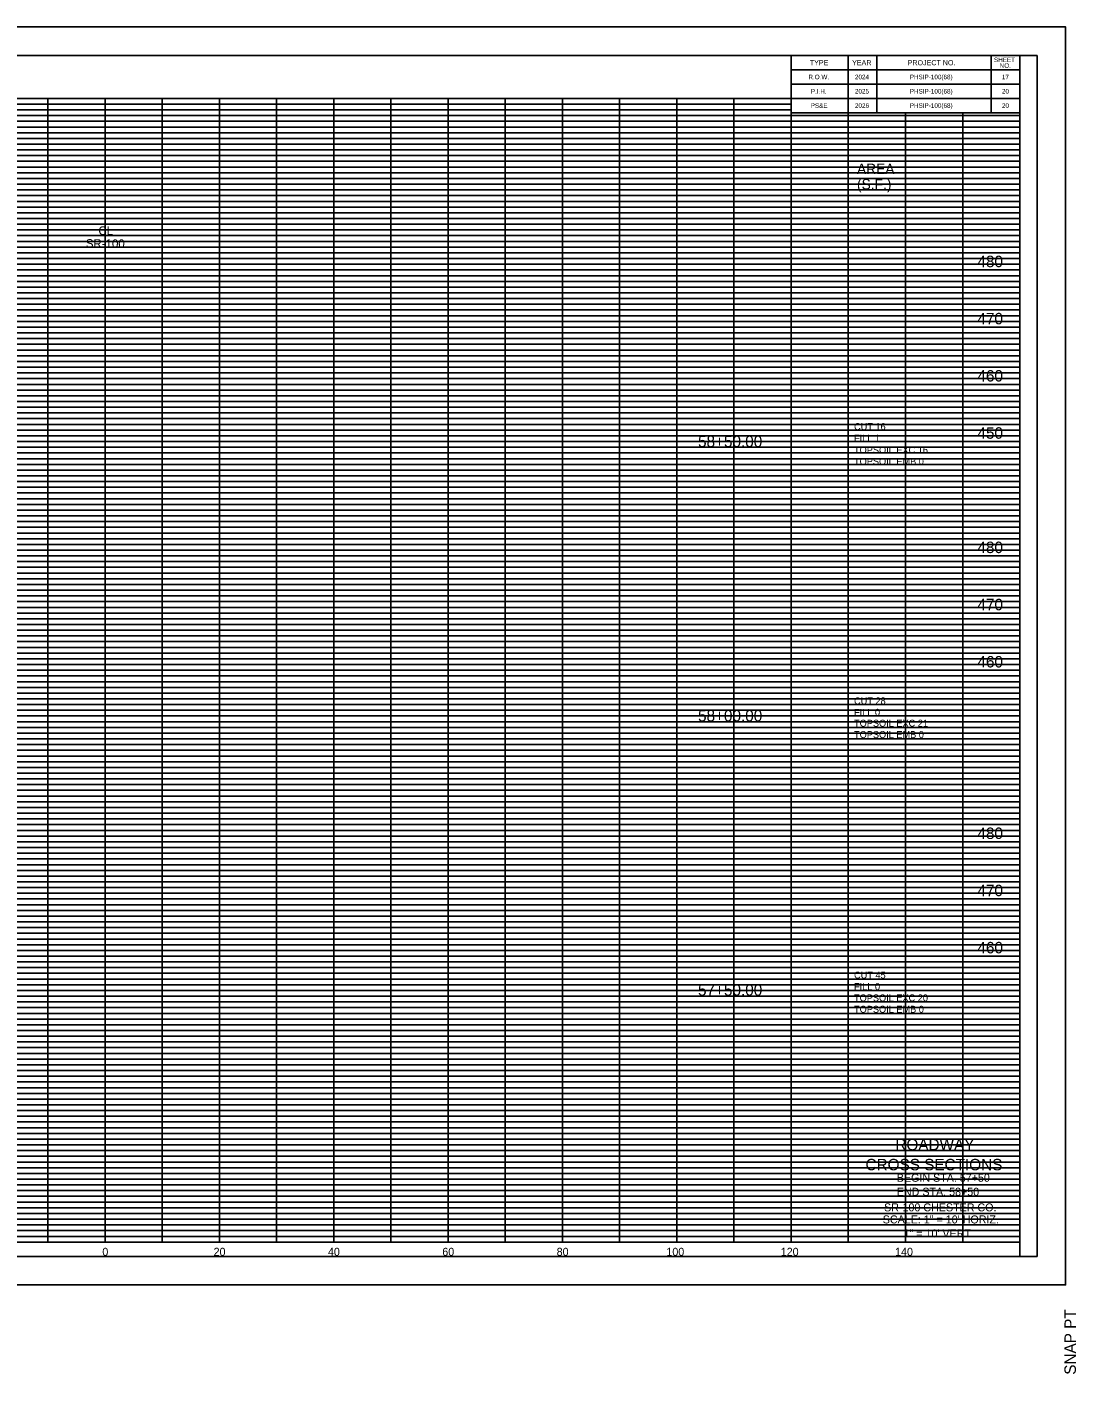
# Model space of a CAD drawing. Extents: x 37 to 1710, y 707 to 2305.
# Drawn here: x 1146.3 to 1329.8, y 976.9 to 1212.5 of the extents above; entities that cross this region are included whole.
import ezdxf

# ---------------------------------------------------------------- set-up
doc = ezdxf.new("R2010")
doc.units = 0
for name, color, linetype in [('DESIGN - DRAINAGE - Special Ditch Width Text', 7, 'Continuous'), ('DESIGN - SCRATCH - User 1', 7, 'Continuous'), ('DESIGN - SHEET - Corner Text', 7, 'Continuous'), ('DESIGN - SHEET - Light Grid', 7, 'Continuous'), ('DESIGN - SHEET - Linework', 7, 'Continuous'), ('DESIGN - SHEET - Plot Shape', 7, 'Continuous'), ('DESIGN - TYPICAL - Text', 7, 'Continuous')]:
    doc.layers.add(name, color=color, linetype=linetype)

msp = doc.modelspace()

# ---------------------------------------------------------------- linework, layer by layer
at = {"layer": 'DESIGN - SCRATCH - User 1'}
for p, q in [((1285, 1203.75), (1285, 1203.75)), ((1292.5, 1203.75), (1292.5, 1203.75)), ((1305, 1203.75), (1305, 1203.75)), ((1317.5, 1203.75), (1317.5, 1203.75)), ((1285, 1201.25), (1285, 1201.25)), ((1292.5, 1201.25), (1292.5, 1201.25)), ((1305, 1201.25), (1305, 1201.25)), ((1317.5, 1201.25), (1317.5, 1201.25))]:
    msp.add_line(p, q, dxfattribs=at)
at = {"layer": 'DESIGN - SHEET - Light Grid'}
for p, q in [((1000, 1199), (1280, 1199)), ((1000, 1198), (1280, 1198)), ((1000, 1197), (1320, 1197)), ((1000, 1196), (1320, 1196)), ((1000, 1195), (1320, 1195)), ((1000, 1194), (1320, 1194)), ((1000, 1193), (1320, 1193)), ((1000, 1192), (1320, 1192)), ((1000, 1191), (1320, 1191)), ((1000, 1189), (1320, 1189)), ((1000, 1188), (1320, 1188)), ((1000, 1187), (1320, 1187)), ((1000, 1186), (1320, 1186)), ((1000, 1185), (1320, 1185)), ((1000, 1184), (1320, 1184)), ((1000, 1183), (1320, 1183)), ((1000, 1182), (1320, 1182)), ((1000, 1181), (1320, 1181)), ((1000, 1179), (1320, 1179)), ((1000, 1178), (1320, 1178)), ((1000, 1177), (1320, 1177)), ((1000, 1176), (1320, 1176)), ((1000, 1175), (1320, 1175)), ((1000, 1174), (1320, 1174)), ((1000, 1173), (1320, 1173)), ((1000, 1172), (1320, 1172)), ((1000, 1171), (1320, 1171)), ((1000, 1169), (1320, 1169)), ((1000, 1168), (1320, 1168)), ((1000, 1167), (1320, 1167)), ((1000, 1166), (1320, 1166)), ((1000, 1165), (1320, 1165)), ((1000, 1164), (1320, 1164)), ((1000, 1163), (1320, 1163)), ((1000, 1162), (1320, 1162)), ((1000, 1161), (1320, 1161)), ((1000, 1159), (1320, 1159)), ((1000, 1158), (1320, 1158)), ((1000, 1157), (1320, 1157)), ((1000, 1156), (1320, 1156)), ((1000, 1155), (1320, 1155)), ((1000, 1154), (1320, 1154)), ((1000, 1153), (1320, 1153)), ((1000, 1152), (1320, 1152)), ((1000, 1151), (1320, 1151)), ((1000, 1149), (1320, 1149)), ((1000, 1148), (1320, 1148)), ((1000, 1147), (1320, 1147)), ((1000, 1146), (1320, 1146)), ((1000, 1145), (1320, 1145)), ((1000, 1144), (1320, 1144)), ((1000, 1143), (1320, 1143)), ((1000, 1142), (1320, 1142)), ((1000, 1141), (1320, 1141)), ((1000, 1139), (1320, 1139)), ((1000, 1138), (1320, 1138)), ((1000, 1137), (1320, 1137)), ((1000, 1136), (1320, 1136)), ((1000, 1135), (1320, 1135)), ((1000, 1134), (1320, 1134)), ((1000, 1133), (1320, 1133)), ((1000, 1132), (1320, 1132)), ((1000, 1131), (1320, 1131)), ((1000, 1129), (1320, 1129)), ((1000, 1128), (1320, 1128)), ((1000, 1127), (1320, 1127)), ((1000, 1126), (1320, 1126)), ((1000, 1125), (1320, 1125)), ((1000, 1124), (1320, 1124)), ((1000, 1123), (1320, 1123)), ((1000, 1122), (1320, 1122)), ((1000, 1121), (1320, 1121)), ((1000, 1119), (1320, 1119)), ((1000, 1118), (1320, 1118)), ((1000, 1117), (1320, 1117)), ((1000, 1116), (1320, 1116)), ((1000, 1115), (1320, 1115)), ((1000, 1114), (1320, 1114)), ((1000, 1113), (1320, 1113)), ((1000, 1112), (1320, 1112)), ((1000, 1111), (1320, 1111)), ((1000, 1109), (1320, 1109)), ((1000, 1108), (1320, 1108)), ((1000, 1107), (1320, 1107)), ((1000, 1106), (1320, 1106)), ((1000, 1105), (1320, 1105)), ((1000, 1104), (1320, 1104)), ((1000, 1103), (1320, 1103)), ((1000, 1102), (1320, 1102)), ((1000, 1101), (1320, 1101)), ((1000, 1099), (1320, 1099)), ((1000, 1098), (1320, 1098)), ((1000, 1097), (1320, 1097)), ((1000, 1096), (1320, 1096)), ((1000, 1095), (1320, 1095)), ((1000, 1094), (1320, 1094)), ((1000, 1093), (1320, 1093)), ((1000, 1092), (1320, 1092)), ((1000, 1091), (1320, 1091)), ((1000, 1089), (1320, 1089)), ((1000, 1088), (1320, 1088)), ((1000, 1087), (1320, 1087)), ((1000, 1086), (1320, 1086)), ((1000, 1085), (1320, 1085)), ((1000, 1084), (1320, 1084)), ((1000, 1083), (1320, 1083)), ((1000, 1082), (1320, 1082)), ((1000, 1081), (1320, 1081)), ((1000, 1079), (1320, 1079)), ((1000, 1078), (1320, 1078)), ((1000, 1077), (1320, 1077)), ((1000, 1076), (1320, 1076)), ((1000, 1075), (1320, 1075)), ((1000, 1074), (1320, 1074)), ((1000, 1073), (1320, 1073)), ((1000, 1072), (1320, 1072)), ((1000, 1071), (1320, 1071)), ((1000, 1069), (1320, 1069)), ((1000, 1068), (1320, 1068)), ((1000, 1067), (1320, 1067)), ((1000, 1066), (1320, 1066)), ((1000, 1065), (1320, 1065)), ((1000, 1064), (1320, 1064)), ((1000, 1063), (1320, 1063)), ((1000, 1062), (1320, 1062)), ((1000, 1061), (1320, 1061)), ((1000, 1059), (1320, 1059)), ((1000, 1058), (1320, 1058)), ((1000, 1057), (1320, 1057)), ((1000, 1056), (1320, 1056)), ((1000, 1055), (1320, 1055)), ((1000, 1054), (1320, 1054)), ((1000, 1053), (1320, 1053)), ((1000, 1052), (1320, 1052)), ((1000, 1051), (1320, 1051)), ((1000, 1049), (1320, 1049)), ((1000, 1048), (1320, 1048)), ((1000, 1047), (1320, 1047)), ((1000, 1046), (1320, 1046)), ((1000, 1045), (1320, 1045)), ((1000, 1044), (1320, 1044)), ((1000, 1043), (1320, 1043)), ((1000, 1042), (1320, 1042)), ((1000, 1041), (1320, 1041)), ((1000, 1039), (1320, 1039)), ((1000, 1038), (1320, 1038)), ((1000, 1037), (1320, 1037)), ((1000, 1036), (1320, 1036)), ((1000, 1035), (1320, 1035)), ((1000, 1034), (1320, 1034)), ((1000, 1033), (1320, 1033)), ((1000, 1032), (1320, 1032)), ((1000, 1031), (1320, 1031)), ((1000, 1029), (1320, 1029)), ((1000, 1028), (1320, 1028)), ((1000, 1027), (1320, 1027)), ((1000, 1026), (1320, 1026)), ((1000, 1025), (1320, 1025)), ((1000, 1024), (1320, 1024)), ((1000, 1023), (1320, 1023)), ((1000, 1022), (1320, 1022)), ((1000, 1021), (1320, 1021)), ((1000, 1019), (1320, 1019)), ((1000, 1018), (1320, 1018)), ((1000, 1017), (1320, 1017)), ((1000, 1016), (1320, 1016)), ((1000, 1015), (1320, 1015)), ((1000, 1014), (1320, 1014)), ((1000, 1013), (1320, 1013)), ((1000, 1012), (1320, 1012)), ((1000, 1011), (1320, 1011)), ((1000, 1009), (1320, 1009)), ((1000, 1008), (1320, 1008)), ((1000, 1007), (1320, 1007)), ((1000, 1006), (1320, 1006)), ((1000, 1005), (1320, 1005)), ((1000, 1004), (1320, 1004)), ((1000, 1003), (1320, 1003)), ((1000, 1002), (1320, 1002)), ((1000, 1001), (1320, 1001))]:
    msp.add_line(p, q, dxfattribs=at)
at = {"layer": 'DESIGN - SHEET - Linework'}
for p, q in [((1320, 1207.5), (1280, 1207.5)), ((1280, 1200), (1280, 1207.5)), ((1290, 1200), (1290, 1207.5)), ((1295, 1197.5), (1295, 1207.5)), ((1315, 1197.5), (1315, 1207.5)), ((1320, 1200), (1320, 1207.5)), ((1320, 1205), (1280, 1205)), ((1320, 1202.5), (1280, 1202.5)), ((1000, 1200), (1320, 1200)), ((1150, 1000), (1150, 1200)), ((1160, 1000), (1160, 1200)), ((1170, 1000), (1170, 1200)), ((1180, 1000), (1180, 1200)), ((1190, 1000), (1190, 1200)), ((1200, 1000), (1200, 1200)), ((1210, 1000), (1210, 1200)), ((1220, 1000), (1220, 1200)), ((1230, 1000), (1230, 1200)), ((1240, 1000), (1240, 1200)), ((1250, 1000), (1250, 1200)), ((1260, 1000), (1260, 1200)), ((1270, 1000), (1270, 1200)), ((1280, 1000), (1280, 1200)), ((1290, 1000), (1290, 1200)), ((1320, 1197.5), (1280, 1197.5)), ((1300, 1000), (1300, 1197.5)), ((1310, 1000), (1310, 1197.5)), ((1000, 1190), (1320, 1190)), ((1000, 1180), (1320, 1180)), ((1000, 1170), (1320, 1170)), ((1000, 1160), (1320, 1160)), ((1000, 1150), (1320, 1150)), ((1000, 1140), (1320, 1140)), ((1000, 1130), (1320, 1130)), ((1000, 1120), (1320, 1120)), ((1000, 1110), (1320, 1110)), ((1000, 1100), (1320, 1100)), ((1000, 1090), (1320, 1090)), ((1000, 1080), (1320, 1080)), ((1000, 1070), (1320, 1070)), ((1000, 1060), (1320, 1060)), ((1000, 1050), (1320, 1050)), ((1000, 1040), (1320, 1040)), ((1000, 1030), (1320, 1030)), ((1000, 1020), (1320, 1020)), ((1000, 1010), (1320, 1010)), ((1000, 1000), (1320, 1000))]:
    msp.add_line(p, q, dxfattribs=at)
for points in [[(988, 1212.5), (1328, 1212.5), (1328, 992.5), (988, 992.5)], [(1000, 1207.5), (1320, 1207.5), (1320, 997.5), (1000, 997.5)]]:
    msp.add_lwpolyline(points, close=True, dxfattribs=at)
at = {"layer": 'DESIGN - SHEET - Plot Shape'}
msp.add_lwpolyline([(993, 1207.5), (1323, 1207.5), (1323, 997.5), (993, 997.5)], close=True, dxfattribs=at)

# ---------------------------------------------------------------- texts
at = {"layer": 'DESIGN - DRAINAGE - Special Ditch Width Text'}
for s, p in [('CL', (1158.85, 1176.13)), ('SR-100', (1156.64, 1173.89))]:
    msp.add_text(s, height=1.5, rotation=359.6675, dxfattribs=at).set_placement(p)
at = {"layer": 'DESIGN - SHEET - Corner Text'}
for s, height, p in [('R.O.W.', 0.8, (1283.02, 1203.35)), ('2024', 0.8, (1291.16, 1203.35)), ('PHSIP-100(68)', 0.8, (1300.75, 1203.35)), ('17', 0.8, (1316.86, 1203.35)), ('P.I.H.', 0.8, (1283.45, 1200.85)), ('2025', 0.8, (1291.16, 1200.85)), ('PHSIP-100(68)', 0.8, (1300.75, 1200.85)), ('20', 0.8, (1316.87, 1200.85)), ('PS&E', 0.8, (1283.42, 1198.35)), ('2026', 0.8, (1291.16, 1198.35)), ('PHSIP-100(68)', 0.8, (1300.75, 1198.35)), ('20', 0.8, (1316.87, 1198.35)), ('ROADWAY ', 2, (1298.23, 1016.05)), ('CROSS SECTIONS', 2, (1293.01, 1012.55)), ('BEGIN STA. 57+50', 1.4, (1298.47, 1010.55)), ('END STA. 58+50', 1.4, (1298.47, 1008.1)), ('SR-100 CHESTER CO.', 1.4, (1296.25, 1005.37)), ('SCALE: 1" = 10\' HORIZ.', 1.4, (1296.02, 1003.26)), ('       1" = 10\' VERT.   ', 1.4, (1296.02, 1000.81))]:
    msp.add_text(s, height=height, dxfattribs=at).set_placement(p)
msp.add_text('SNAP PT  ', height=2, rotation=90, dxfattribs=at).set_placement((1329.8, 976.8))
at = {"layer": 'DESIGN - SHEET - Light Grid'}
for s, height, p in [('TYPE', 0.9, (1283.26, 1205.8)), ('YEAR', 0.9, (1290.66, 1205.8)), ('PROJECT NO.', 0.9, (1300.38, 1205.8)), ('SHEET', 0.8, (1315.47, 1206.35)), ('NO.', 0.8, (1316.47, 1205.35))]:
    msp.add_text(s, height=height, dxfattribs=at).set_placement(p)
at = {"layer": 'DESIGN - TYPICAL - Text'}
for s, height, p in [('AREA ', 1.8, (1291.52, 1186.79)), ('(S.F.)', 1.8, (1291.52, 1184.09)), ('     480     ', 2, (1308.87, 1170.49)), ('     470     ', 2, (1308.87, 1160.49)), ('     460     ', 2, (1308.87, 1150.49)), ('CUT 16', 1.2, (1291, 1142.02)), ('     58+50.00     ', 2, (1260, 1139.02)), ('FILL 1', 1.2, (1291, 1140.02)), ('     450     ', 2, (1308.87, 1140.49)), ('TOPSOIL EXC 16', 1.2, (1291, 1137.92)), ('TOPSOIL EMB 0', 1.2, (1291, 1135.93)), ('     480     ', 2, (1308.87, 1120.49)), ('     470     ', 2, (1308.87, 1110.49)), ('     460     ', 2, (1308.87, 1100.49)), ('CUT 28', 1.2, (1291, 1094.05)), ('FILL 0', 1.2, (1291, 1092.05)), ('     58+00.00     ', 2, (1260, 1091.05)), ('TOPSOIL EXC 21', 1.2, (1291, 1090.14)), ('TOPSOIL EMB 0', 1.2, (1291, 1088.16)), ('     480     ', 2, (1308.87, 1070.49)), ('     470     ', 2, (1308.87, 1060.49)), ('     460     ', 2, (1308.87, 1050.49)), ('CUT 45', 1.2, (1291, 1046.09)), ('     57+50.00     ', 2, (1260, 1043.09)), ('FILL 0', 1.2, (1291, 1044.09)), ('TOPSOIL EXC 20', 1.2, (1291, 1042.11)), ('TOPSOIL EMB 0', 1.2, (1291, 1040.12)), ('     0     ', 1.4, (1156.93, 997.6)), ('     0     ', 1.4, (1156.93, 997.6)), ('     20     ', 1.4, (1176.39, 997.6)), ('     40     ', 1.4, (1196.39, 997.6)), ('     60     ', 1.4, (1216.39, 997.6)), ('     80     ', 1.4, (1236.39, 997.6)), ('     100     ', 1.4, (1255.58, 997.6)), ('     120     ', 1.4, (1275.58, 997.6)), ('     140     ', 1.4, (1295.58, 997.6))]:
    msp.add_text(s, height=height, dxfattribs=at).set_placement(p)

doc.saveas('drawing.dxf')
